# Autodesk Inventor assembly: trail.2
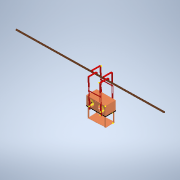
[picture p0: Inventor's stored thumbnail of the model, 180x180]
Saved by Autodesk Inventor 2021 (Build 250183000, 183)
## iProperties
Created: 2021-07
Part Number: trail.2
Document SubType Name: Assembly
Designer: CHIRAG
Author: CHIRAG
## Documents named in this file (17)
- C:\Users\CHIRAG\Downloads\trail.2.iam
- C:\Users\CHIRAG\Documents\Assembly2\Assembly2\trail.2\Design Accelerator\Spur Gears4.iam
- C:\Users\CHIRAG\Documents\Assembly2\Assembly2\trail.2\Design Accelerator\Spur Gears5.iam
- C:\Users\CHIRAG\Documents\Assembly2\Assembly2\trail.2\Design Accelerator\Spur Gears6.iam
- C:\Users\CHIRAG\Downloads\Shaft1.ipt
- C:\Users\CHIRAG\Documents\Assembly2\Assembly2\Part7.ipt
- C:\Users\CHIRAG\Downloads\Shaft6.ipt
- C:\Users\CHIRAG\Downloads\Shaft4.ipt
- C:\Users\CHIRAG\Documents\Assembly2\Assembly2\trail.part1_CPY.ipt
- C:\Users\CHIRAG\Documents\Assembly2\Assembly2\Shaft12_CPY_CPY.ipt
- C:\Users\CHIRAG\Documents\Assembly2\Assembly2\Part.trail.2.ipt
- C:\Users\CHIRAG\Downloads\Shaft8.ipt
- C:\Users\CHIRAG\Documents\Assembly2\Assembly2\Shaft13.ipt
- C:\Users\CHIRAG\Documents\Assembly2\Assembly2\outer frame.ipt
- C:\Users\CHIRAG\Documents\Assembly2\Assembly2\box cover.ipt
- C:\Users\CHIRAG\Documents\Assembly2\Assembly2\xyz.ipt
- C:\Users\CHIRAG\Downloads\Shaft9.ipt
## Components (24 placed, 8 different names)
1. Spur Gears:1 [sub-assembly] — Mate:3, Flush:1, Mate:4, Rotation:2, Mate:29, Flush:6
2. Spur Gears:2 [sub-assembly] — Mate:1, Mate:2, Mate:3, Flush:1, Rotation:2, Mate:13, Mate:15, Flush:2, Rotation:3, Angle:1, Rigid:1
3. Spur Gears:3 [sub-assembly] — Flush:2, Mate:16, Mate:17, Rotation:3, Rotational:2, Rotational:3, Mate:27, Flush:5
4. Shaft:1
5. Part7:1
6. Shaft:1
7. Shaft:2 — Rigid:1
8. Shaft:5 — Rotational:2, Mate:18, Flush:3, Flush:10
9. trail.part1_CPY:5 — Mate:21, Mate:22, Flush:8, Flush:9
10. trail.part1_CPY:6 — Mate:18, Mate:19, Flush:3, Flush:10
11. Shaft:1
12. Shaft:8 — Mate:19
13. Shaft:9 — Rotational:3, Mate:22, Flush:8
14. Shaft:10 — Mate:21, Flush:9
15. outer frame:1 — Mate:23, Mate:24, Mate:25, Mate:26, Rotational:6, Rotational:7
16. Part.trail.2:1 — Mate:25
17. box cover:1 — Mate:23, Mate:24, Mate:26
18. Spur Gears:4 [sub-assembly] — Mate:28, Flush:4
19. Spur Gears:5 [sub-assembly] — Mate:30, Flush:7
20. xyz:1
21. Shaft:14 — Mate:29, Flush:6, Mate:30, Flush:7
22. Shaft:16 — Mate:27, Mate:28, Flush:4, Flush:5
23. Shaft:1 — Rotational:6
24. Shaft:17 — Rotational:7
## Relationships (38: Mate 20, Flush 10, RevoluteJoint 4, RelateRotation 2, Angle 1, WeldJoint 1)
- Mate:1: Spur Gears:2
- Mate:2: Spur Gears:2
- Mate:3: Spur Gears:1 ↔ Spur Gears:2
- Flush:1: Spur Gears:1 ↔ Spur Gears:2
- Mate:4: Spur Gears:1
- Rotation:2 [RelateRotation]: Spur Gears:1 ↔ Spur Gears:2
- Mate:13: Spur Gears:2
- Mate:15: Spur Gears:2
- Flush:2: Spur Gears:2 ↔ Spur Gears:3
- Mate:16: Spur Gears:3
- Mate:17: Spur Gears:3
- Rotation:3 [RelateRotation]: Spur Gears:2 ↔ Spur Gears:3
- Angle:1: Spur Gears:2
- Rigid:1 [WeldJoint]: Spur Gears:2 ↔ Shaft:2
- Rotational:2 [RevoluteJoint]: Spur Gears:3 ↔ Shaft:5
- Mate:18: Shaft:5 ↔ trail.part1_CPY:6
- Mate:19: trail.part1_CPY:6 ↔ Shaft:8
- Flush:3: Shaft:5 ↔ trail.part1_CPY:6
- Mate:21: trail.part1_CPY:5 ↔ Shaft:10
- Rotational:3 [RevoluteJoint]: Spur Gears:3 ↔ Shaft:9
- Mate:22: trail.part1_CPY:5 ↔ Shaft:9
- Mate:23: outer frame:1 ↔ box cover:1
- Mate:24: outer frame:1 ↔ box cover:1
- Mate:25: outer frame:1 ↔ Part.trail.2:1
- Mate:26: outer frame:1 ↔ box cover:1
- Rotational:6 [RevoluteJoint]: outer frame:1 ↔ Shaft:1
- Rotational:7 [RevoluteJoint]: outer frame:1 ↔ Shaft:17
- Mate:27: Spur Gears:3 ↔ Shaft:16
- Mate:28: Spur Gears:4 ↔ Shaft:16
- Flush:4: Spur Gears:4 ↔ Shaft:16
- Flush:5: Spur Gears:3 ↔ Shaft:16
- Mate:29: Spur Gears:1 ↔ Shaft:14
- Flush:6: Spur Gears:1 ↔ Shaft:14
- Mate:30: Spur Gears:5 ↔ Shaft:14
- Flush:7: Spur Gears:5 ↔ Shaft:14
- Flush:8: trail.part1_CPY:5 ↔ Shaft:9
- Flush:9: trail.part1_CPY:5 ↔ Shaft:10
- Flush:10: Shaft:5 ↔ trail.part1_CPY:6
